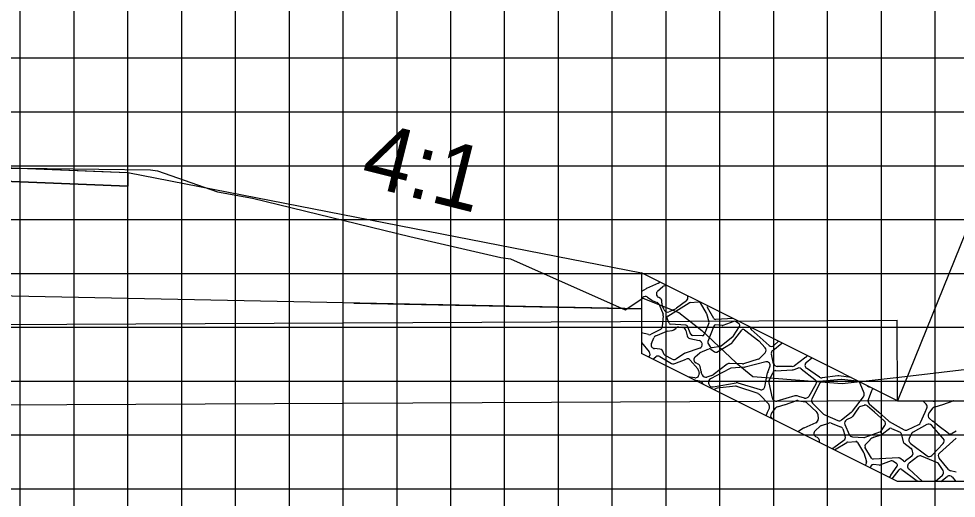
# Model space of a CAD drawing. Extents: x 851348 to 851692, y 364785 to 365005.
# Drawn here: x 851532.16 to 851549.58, y 364815.06 to 364823.96 of the extents above; entities that cross this region are included whole.
import ezdxf

# ---------------------------------------------------------------- set-up
doc = ezdxf.new("R2010")
doc.units = 0
for name, color, linetype in [('ANNOTATION', 7, 'Continuous'), ('D_Drainage_Culvert', 7, 'Continuous'), ('D_Roadway_Centerline', 7, 'Continuous'), ('D_Roadway_Edge_Shoulder', 7, 'Continuous'), ('D_Roadway_SubGrade', 7, 'Continuous'), ('MAJOR', 7, 'Continuous'), ('MINOR', 7, 'Continuous'), ('S_Roadway_Centerline', 7, 'Continuous')]:
    doc.layers.add(name, color=color, linetype=linetype)

msp = doc.modelspace()

# ---------------------------------------------------------------- linework, layer by layer
at = {"layer": 'ANNOTATION'}
for p, q in [((851545.52, 364818.351), (851543.731, 364819.245)), ((851543.731, 364819.245), (851543.731, 364817.745)), ((851538.389, 364818.681), (851543.731, 364818.574))]:
    msp.add_line(p, q, dxfattribs=at)
for points in [[(851556.942, 364823.691), (851551.251, 364823.691), (851548.49, 364816.866)], [(851534.191, 364821.105), (851543.731, 364819.245)], [(851548.49, 364816.866), (851550.49, 364816.866), (851552.49, 364817.866), (851556.563, 364819.902)], [(851548.49, 364816.866), (851546.49, 364817.866), (851545.52, 364818.351)], [(851548.49, 364815.366), (851543.731, 364817.745)], [(851550.49, 364815.366), (851548.49, 364815.366)]]:
    msp.add_lwpolyline(points, dxfattribs=at)
at = {"layer": 'D_Drainage_Culvert'}
for p, q in [((851480.479, 364818.026), (851548.483, 364818.366)), ((851548.49, 364816.866), (851548.483, 364818.366)), ((851548.49, 364816.866), (851480.463, 364816.525))]:
    msp.add_line(p, q, dxfattribs=at)
at = {"layer": 'D_Roadway_Centerline'}
msp.add_lwpolyline([(851485.104, 364818.833), (851493.575, 364820.951), (851494.191, 364821.105), (851501.707, 364821.405), (851502.191, 364821.425), (851513.465, 364821.65), (851514.191, 364821.665), (851525.465, 364821.439), (851526.191, 364821.425), (851533.707, 364821.124), (851534.191, 364821.105), (851543.731, 364819.245)], dxfattribs=at)
at = {"layer": 'D_Roadway_Edge_Shoulder'}
msp.add_lwpolyline([(851526.191, 364821.425), (851534.191, 364821.105), (851534.191, 364820.855), (851526.191, 364821.175)], close=True, dxfattribs=at)
at = {"layer": 'D_Roadway_SubGrade'}
for p, q in [((851543.819, 364818.948), (851543.731, 364818.896)), ((851544.049, 364819.051), (851543.826, 364818.951)), ((851544.033, 364818.902), (851544.129, 364818.986)), ((851544.152, 364818.999), (851544.195, 364819.013)), ((851543.731, 364818.761), (851543.759, 364818.786)), ((851543.843, 364818.79), (851543.922, 364818.734)), ((851544.076, 364818.774), (851544.046, 364818.79)), ((851544.586, 364818.818), (851544.592, 364818.8)), ((851543.934, 364818.728), (851544.023, 364818.689)), ((851544.059, 364818.652), (851544.133, 364818.474)), ((851544.119, 364818.643), (851544.113, 364818.72)), ((851544.154, 364818.556), (851544.125, 364818.622)), ((851544.221, 364818.44), (851544.62, 364818.685)), ((851544.37, 364818.576), (851544.244, 364818.52)), ((851544.568, 364818.723), (851544.384, 364818.584)), ((851544.635, 364818.69), (851544.791, 364818.702)), ((851544.823, 364818.686), (851544.935, 364818.496)), ((851545.079, 364818.392), (851544.96, 364818.599)), ((851544.138, 364818.442), (851544.12, 364818.246)), ((851544.244, 364818.308), (851544.207, 364818.397)), ((851544.938, 364818.489), (851544.986, 364818.33)), ((851545.438, 364818.392), (851545.111, 364818.374)), ((851544.557, 364818.271), (851544.274, 364818.287)), ((851544.336, 364818.184), (851544.374, 364818.217)), ((851544.425, 364818.233), (851544.498, 364818.225)), ((851544.652, 364818.1), (851544.586, 364818.25)), ((851544.985, 364818.307), (851544.9, 364818.095)), ((851545.075, 364818.253), (851544.965, 364817.968)), ((851545.231, 364818.263), (851545.11, 364818.274)), ((851545.449, 364818.34), (851545.246, 364818.265)), ((851545.442, 364818.074), (851545.556, 364818.245)), ((851545.547, 364818.292), (851545.48, 364818.337)), ((851543.864, 364818.095), (851543.731, 364818.13)), ((851544.084, 364818.192), (851543.914, 364818.101)), ((851543.998, 364818.072), (851544.191, 364818.153)), ((851544.209, 364818.157), (851544.3, 364818.169)), ((851544.558, 364818.172), (851544.579, 364818.075)), ((851544.867, 364818.074), (851544.682, 364818.08)), ((851545.216, 364817.889), (851545.435, 364818.066)), ((851545.424, 364817.953), (851545.596, 364818.178)), ((851545.644, 364818.184), (851545.91, 364817.981)), ((851545.773, 364818.191), (851546.102, 364817.894)), ((851543.731, 364817.95), (851543.877, 364817.773)), ((851543.916, 364817.932), (851543.962, 364818.037)), ((851544.632, 364818.022), (851544.803, 364817.987)), ((851544.856, 364817.936), (851544.858, 364817.925)), ((851544.968, 364817.938), (851545.008, 364817.87)), ((851545.043, 364817.854), (851545.2, 364817.882)), ((851545.13, 364817.771), (851545.415, 364817.945)), ((851545.915, 364817.977), (851546.03, 364817.852)), ((851546.17, 364817.802), (851546.343, 364817.939)), ((851546.193, 364817.893), (851546.281, 364817.97)), ((851544.074, 364817.826), (851543.972, 364817.836)), ((851544.135, 364817.761), (851544.135, 364817.766)), ((851544.304, 364817.638), (851544.171, 364817.709)), ((851544.533, 364817.744), (851544.373, 364817.641)), ((851544.815, 364817.845), (851544.547, 364817.751)), ((851544.73, 364817.682), (851544.815, 364817.759)), ((851544.825, 364817.765), (851544.987, 364817.828)), ((851545.02, 364817.824), (851545.092, 364817.772)), ((851546.03, 364817.758), (851545.932, 364817.655)), ((851546.188, 364817.555), (851546.146, 364817.732)), ((851543.945, 364817.638), (851543.997, 364817.681)), ((851544.074, 364817.687), (851544.292, 364817.561)), ((851544.351, 364817.556), (851544.563, 364817.639)), ((851544.64, 364817.62), (851544.777, 364817.46)), ((851544.787, 364817.548), (851544.744, 364817.57)), ((851545.326, 364817.545), (851545.063, 364817.347)), ((851545.609, 364817.552), (851545.369, 364817.558)), ((851545.902, 364817.637), (851545.631, 364817.555)), ((851546.04, 364817.587), (851545.656, 364817.492)), ((851546.656, 364817.576), (851546.574, 364817.517)), ((851546.789, 364817.674), (851546.656, 364817.576)), ((851546.795, 364817.579), (851546.898, 364817.662)), ((851544.793, 364817.427), (851544.802, 364817.373)), ((851544.841, 364817.409), (851544.822, 364817.501)), ((851544.862, 364817.349), (851544.844, 364817.4)), ((851545.366, 364817.462), (851545.012, 364817.275)), ((851545.645, 364817.491), (851545.393, 364817.47)), ((851546.024, 364817.127), (851546.076, 364817.386)), ((851546.08, 364817.399), (851546.12, 364817.495)), ((851546.106, 364817.24), (851546.17, 364817.384)), ((851546.23, 364817.425), (851546.532, 364817.438)), ((851546.534, 364817.504), (851546.255, 364817.503)), ((851546.552, 364817.442), (851546.636, 364817.471)), ((851546.701, 364817.461), (851546.956, 364817.263)), ((851547.042, 364817.302), (851546.799, 364817.469)), ((851544.725, 364817.294), (851544.596, 364817.313)), ((851544.816, 364817.231), (851544.742, 364817.24)), ((851544.878, 364817.172), (851544.872, 364817.188)), ((851545.042, 364817.336), (851544.947, 364817.307)), ((851544.978, 364817.196), (851544.984, 364817.173)), ((851545.062, 364817.124), (851545.491, 364817.201)), ((851545.523, 364817.199), (851545.938, 364817.074)), ((851546.164, 364816.912), (851546.102, 364817.197)), ((851546.973, 364817.175), (851546.841, 364816.948)), ((851547.047, 364817.193), (851546.898, 364816.901)), ((851547.379, 364817.331), (851547.09, 364817.291)), ((851547.442, 364817.264), (851547.101, 364817.23)), ((851547.628, 364817.297), (851547.399, 364817.331)), ((851547.741, 364817.231), (851547.457, 364817.264)), ((851547.867, 364817.006), (851547.797, 364817.188)), ((851545.477, 364817.137), (851545.137, 364817.098)), ((851545.9, 364816.998), (851545.507, 364817.133)), ((851548.005, 364817.053), (851547.944, 364816.884)), ((851546.096, 364816.803), (851545.927, 364816.98)), ((851546.584, 364816.957), (851546.25, 364816.861)), ((851546.409, 364816.797), (851546.601, 364816.865)), ((851546.656, 364816.947), (851546.622, 364816.957)), ((851546.636, 364816.868), (851546.656, 364816.865)), ((851546.763, 364816.916), (851546.656, 364816.947)), ((851546.656, 364816.865), (851546.772, 364816.845)), ((851546.807, 364816.827), (851546.984, 364816.662)), ((851547.651, 364816.674), (851547.857, 364816.939)), ((851549.02, 364816.803), (851548.96, 364816.866)), ((851549.19, 364816.866), (851549.174, 364816.861)), ((851549.334, 364816.797), (851549.526, 364816.865)), ((851549.575, 364816.866), (851549.58, 364816.865)), ((851546.048, 364816.587), (851546.076, 364816.653)), ((851546.076, 364816.653), (851546.109, 364816.729)), ((851546.146, 364816.63), (851546.164, 364816.653)), ((851546.164, 364816.653), (851546.226, 364816.733)), ((851546.262, 364816.756), (851546.404, 364816.795)), ((851546.91, 364816.821), (851547.078, 364816.653)), ((851547.078, 364816.653), (851547.115, 364816.617)), ((851547.451, 364816.511), (851547.628, 364816.653)), ((851547.628, 364816.653), (851547.64, 364816.662)), ((851547.709, 364816.653), (851547.66, 364816.58)), ((851547.765, 364816.734), (851547.709, 364816.653)), ((851547.867, 364816.781), (851547.801, 364816.761)), ((851548.062, 364816.653), (851547.931, 364816.767)), ((851547.963, 364816.81), (851548.139, 364816.653)), ((851548.243, 364816.495), (851548.062, 364816.653)), ((851548.139, 364816.653), (851548.32, 364816.491)), ((851548.918, 364816.461), (851549.001, 364816.653)), ((851549.001, 364816.653), (851549.033, 364816.729)), ((851549.071, 364816.63), (851549.089, 364816.653)), ((851549.089, 364816.653), (851549.151, 364816.733)), ((851549.187, 364816.756), (851549.329, 364816.795)), ((851546.164, 364816.528), (851546.157, 364816.534)), ((851547.006, 364816.619), (851547.014, 364816.527)), ((851547.137, 364816.602), (851547.382, 364816.501)), ((851547.634, 364816.557), (851547.542, 364816.511)), ((851548.333, 364816.482), (851548.613, 364816.329)), ((851549.142, 364816.486), (851549.082, 364816.534)), ((851549.262, 364816.389), (851549.143, 364816.486)), ((851546.656, 364816.303), (851546.637, 364816.292)), ((851546.743, 364816.355), (851546.656, 364816.303)), ((851546.974, 364816.458), (851546.75, 364816.359)), ((851546.958, 364816.31), (851547.054, 364816.394)), ((851547.077, 364816.407), (851547.211, 364816.452)), ((851547.257, 364816.451), (851547.431, 364816.384)), ((851547.471, 364816.342), (851547.517, 364816.208)), ((851547.51, 364816.423), (851547.591, 364816.237)), ((851548.191, 364816.312), (851548.255, 364816.406)), ((851548.213, 364816.254), (851548.34, 364816.349)), ((851548.375, 364816.353), (851548.537, 364816.281)), ((851548.675, 364816.327), (851548.885, 364816.427)), ((851549.034, 364816.425), (851548.779, 364816.285)), ((851549.34, 364816.163), (851549.118, 364816.41)), ((851549.431, 364816.264), (851549.264, 364816.387)), ((851549.58, 364816.303), (851549.506, 364816.26)), ((851547.001, 364816.182), (851546.971, 364816.198)), ((851547.041, 364816.09), (851547.037, 364816.128)), ((851547.493, 364816.131), (851547.308, 364815.992)), ((851547.65, 364816.196), (851547.862, 364816.184)), ((851547.89, 364816.188), (851548.158, 364816.286)), ((851547.89, 364816.047), (851547.978, 364816.143)), ((851548.047, 364816.188), (851548.167, 364816.23)), ((851548.557, 364816.258), (851548.595, 364816.101)), ((851548.751, 364816.255), (851548.707, 364816.166)), ((851549.268, 364815.895), (851549.58, 364816.169)), ((851547.295, 364815.984), (851547.273, 364815.974)), ((851547.317, 364815.952), (851547.545, 364816.092)), ((851547.56, 364816.097), (851547.715, 364816.11)), ((851547.748, 364816.093), (851547.859, 364815.904)), ((851548.004, 364815.799), (851547.885, 364816.007)), ((851548.608, 364816.082), (851548.744, 364815.982)), ((851548.726, 364816.081), (851549.038, 364815.843)), ((851548.757, 364815.96), (851548.771, 364815.871)), ((851549.129, 364815.85), (851549.338, 364816.07)), ((851547.863, 364815.896), (851547.911, 364815.738)), ((851548.508, 364815.807), (851548.035, 364815.782)), ((851548.598, 364815.748), (851548.531, 364815.8)), ((851548.758, 364815.839), (851548.64, 364815.748)), ((851548.869, 364815.828), (851548.703, 364815.704)), ((851549.23, 364815.711), (851548.937, 364815.836)), ((851549.438, 364815.588), (851549.261, 364815.8)), ((851547.91, 364815.715), (851547.89, 364815.666)), ((851547.999, 364815.661), (851547.983, 364815.619)), ((851548.156, 364815.671), (851548.035, 364815.682)), ((851548.374, 364815.748), (851548.171, 364815.673)), ((851548.367, 364815.481), (851548.481, 364815.653)), ((851548.472, 364815.7), (851548.405, 364815.745)), ((851549.336, 364815.57), (851549.261, 364815.685)), ((851548.327, 364815.447), (851548.36, 364815.474)), ((851548.39, 364815.415), (851548.521, 364815.586)), ((851548.569, 364815.592), (851548.835, 364815.389)), ((851548.698, 364815.599), (851548.956, 364815.366)), ((851549.191, 364815.366), (851549.323, 364815.481)), ((851549.291, 364815.366), (851549.41, 364815.46)), ((851549.58, 364815.538), (851549.473, 364815.566)), ((851549.505, 364815.45), (851549.574, 364815.366)), ((851548.839, 364815.385), (851548.857, 364815.366))]:
    msp.add_line(p, q, dxfattribs=at)
msp.add_lwpolyline([(851485.104, 364818.833), (851494.191, 364821.105), (851494.191, 364820.855), (851502.191, 364821.175), (851514.191, 364821.415), (851526.191, 364821.175), (851534.191, 364820.855), (851534.191, 364821.105), (851543.731, 364819.245), (851543.731, 364818.574), (851526.191, 364818.925), (851514.191, 364819.165), (851502.191, 364818.925), (851485.104, 364818.583)], dxfattribs=at)
for centre, radius, start, end in [((851543.853, 364818.889), 0.0684, 113.9625, 120.6507), ((851544.021, 364819.113), 0.0684, 293.9625, 323.5047), ((851544.174, 364818.934), 0.0684, 108.4349, 131.1859), ((851543.804, 364818.734), 0.0684, 54.7824, 131.257), ((851544.078, 364818.85), 0.0684, 131.1859, 242.3005), ((851544.044, 364818.714), 0.0684, 5.1944, 62.3005), ((851544.527, 364818.778), 0.0684, 307.0199, 18.7413), ((851543.962, 364818.79), 0.0684, 234.7824, 246.3706), ((851543.996, 364818.626), 0.0684, 22.4794, 66.3706), ((851544.188, 364818.649), 0.0684, 185.1944, 203.3852), ((851544.343, 364818.639), 0.0684, 293.8602, 307.0199), ((851544.638, 364818.655), 0.0342, 94.6669, 121.5514), ((851544.793, 364818.668), 0.0342, 30.5102, 94.6669), ((851544.99, 364818.616), 0.0342, 154.1739, 209.792), ((851544.07, 364818.448), 0.0684, 354.8056, 22.4794), ((851544.216, 364818.583), 0.0684, 203.3852, 293.8602), ((851544.239, 364818.411), 0.0342, 121.5514, 202.6199), ((851544.905, 364818.479), 0.0342, 16.9275, 30.5102), ((851545.109, 364818.409), 0.0342, 209.792, 272.9903), ((851544.052, 364818.252), 0.0684, 298.0725, 354.8056), ((851544.276, 364818.321), 0.0342, 202.6199, 266.6726), ((851544.418, 364818.165), 0.0684, 84.2894, 130.3645), ((851544.491, 364818.157), 0.0684, 12.4074, 84.2894), ((851544.555, 364818.237), 0.0342, 23.7495, 86.6726), ((851544.953, 364818.32), 0.0342, 338.1986, 16.9275), ((851545.107, 364818.24), 0.0342, 84.4278, 159.0071), ((851545.234, 364818.297), 0.0342, 264.4278, 290.4835), ((851545.461, 364818.308), 0.0342, 56.3099, 110.4835), ((851545.528, 364818.264), 0.0342, 326.3099, 56.3099), ((851545.819, 364818.242), 0.0684, 185.3373, 227.8776), ((851543.881, 364818.161), 0.0684, 255.2564, 298.0725), ((851544.025, 364818.009), 0.0684, 112.6199, 156.3179), ((851544.218, 364818.089), 0.0684, 97.125, 112.6199), ((851544.292, 364818.237), 0.0684, 277.125, 310.3645), ((851544.646, 364818.089), 0.0684, 192.4074, 258.3664), ((851544.683, 364818.114), 0.0342, 203.7495, 268.1221), ((851544.868, 364818.108), 0.0342, 268.1221, 338.1986), ((851545.414, 364818.093), 0.0342, 308.7742, 326.3099), ((851545.623, 364818.157), 0.0342, 52.5946, 142.5946), ((851543.979, 364817.904), 0.0684, 156.3179, 263.9458), ((851544.789, 364817.92), 0.0684, 13.134, 78.3664), ((851544.792, 364817.909), 0.0684, 289.406, 13.134), ((851544.997, 364817.955), 0.0342, 159.0071, 210.6507), ((851545.037, 364817.888), 0.0342, 210.6507, 280.204), ((851545.194, 364817.916), 0.0342, 280.204, 308.7742), ((851545.397, 364817.974), 0.0342, 301.373, 322.5946), ((851545.89, 364817.954), 0.0342, 42.7891, 52.5946), ((851546.148, 364817.944), 0.0684, 227.8776, 311.2462), ((851543.824, 364817.729), 0.0684, 309.6391, 39.4712), ((851544.04, 364817.628), 0.0684, 59.9314, 128.8845), ((851544.067, 364817.758), 0.0684, 6.8428, 83.9458), ((851544.203, 364817.769), 0.0684, 186.8428, 242.1524), ((851544.57, 364817.686), 0.0684, 109.406, 122.6806), ((851544.838, 364817.734), 0.0342, 111.1941, 132.2073), ((851545, 364817.796), 0.0342, 54.4623, 111.1941), ((851545.112, 364817.8), 0.0342, 234.4623, 301.373), ((851545.98, 364817.805), 0.0684, 316.3639, 42.7891), ((851546.212, 364817.748), 0.0684, 128.373, 193.5819), ((851546.749, 364817.729), 0.0684, 306.2192, 338.5394), ((851544.326, 364817.62), 0.0684, 239.9314, 291.541), ((851544.336, 364817.699), 0.0684, 242.1524, 302.6806), ((851544.588, 364817.576), 0.0684, 40.6013, 111.541), ((851544.776, 364817.631), 0.0684, 132.2073, 242.354), ((851544.755, 364817.487), 0.0684, 11.6336, 62.354), ((851545.367, 364817.49), 0.0684, 88.4306, 126.9888), ((851545.611, 364817.62), 0.0684, 268.4306, 286.8986), ((851545.882, 364817.702), 0.0684, 286.8986, 316.3639), ((851546.057, 364817.521), 0.0684, 337.4775, 103.8595), ((851546.255, 364817.572), 0.0684, 193.5819, 270.0888), ((851546.838, 364817.526), 0.0684, 128.8845, 235.4375), ((851544.735, 364817.361), 0.0684, 261.5289, 10.3048), ((851544.725, 364817.415), 0.0684, 10.3048, 40.6013), ((851544.908, 364817.423), 0.0684, 191.6336, 199.5367), ((851544.926, 364817.372), 0.0684, 199.5367, 287.2815), ((851545.022, 364817.402), 0.0684, 287.2815, 306.9888), ((851545.398, 364817.401), 0.0684, 94.7636, 117.8015), ((851545.64, 364817.559), 0.0684, 274.7636, 283.8595), ((851546.143, 364817.373), 0.0684, 157.4775, 168.7067), ((851546.233, 364817.357), 0.0684, 92.4366, 156.0375), ((851546.529, 364817.506), 0.0684, 272.4366, 289.44), ((851546.534, 364817.572), 0.0684, 270.0888, 306.2192), ((851546.659, 364817.407), 0.0684, 92.6788, 109.44), ((851546.659, 364817.407), 0.0684, 52.3058, 92.6788), ((851544.808, 364817.163), 0.0684, 20.9245, 83.5169), ((851545.044, 364817.214), 0.0684, 117.8015, 195.5241), ((851545.05, 364817.191), 0.0684, 195.5241, 280.1543), ((851545.503, 364817.134), 0.0684, 73.267, 100.1543), ((851546.168, 364817.212), 0.0684, 156.0375, 192.4074), ((851546.914, 364817.209), 0.0684, 329.8265, 52.3058), ((851547.081, 364817.358), 0.0684, 235.4375, 277.9435), ((851547.108, 364817.162), 0.0684, 95.5993, 152.9691), ((851547.389, 364817.263), 0.0684, 81.5289, 97.9435), ((851547.449, 364817.196), 0.0684, 83.5169, 95.5993), ((851547.733, 364817.163), 0.0684, 20.9245, 83.5169), ((851545.145, 364817.03), 0.0684, 96.5245, 147.0214), ((851545.485, 364817.069), 0.0684, 70.9362, 96.5245), ((851545.877, 364816.933), 0.0684, 43.5732, 70.9362), ((851545.957, 364817.14), 0.0684, 253.267, 348.7067), ((851547.803, 364816.981), 0.0684, 322.2243, 20.9245), ((851547.975, 364817.191), 0.0684, 216.5608, 270.3091), ((851548.07, 364817.03), 0.0684, 116.2669, 160.0795), ((851546.231, 364816.927), 0.0684, 192.4074, 285.9454), ((851546.603, 364816.891), 0.0684, 74.0546, 105.9454), ((851546.624, 364816.801), 0.0684, 80.1342, 109.6538), ((851546.782, 364816.982), 0.0684, 254.0546, 329.8265), ((851546.76, 364816.777), 0.0684, 47.1211, 80.1342), ((851546.959, 364816.869), 0.0684, 152.9691, 225), ((851548.009, 364816.861), 0.0684, 160.0795, 228.2412), ((851549.156, 364816.927), 0.0684, 243.4668, 285.9454), ((851549.549, 364816.801), 0.0684, 108.6645, 109.6538), ((851546.046, 364816.756), 0.0684, 336.6444, 43.5732), ((851546.28, 364816.69), 0.0684, 105.2551, 141.953), ((851546.386, 364816.861), 0.0684, 285.2551, 289.6538), ((851546.938, 364816.612), 0.0684, 36.5817, 47.1211), ((851546.938, 364816.612), 0.0684, 5.1944, 36.5817), ((851547.597, 364816.716), 0.0684, 308.6598, 322.2243), ((851547.821, 364816.696), 0.0684, 106.8584, 145.7843), ((851547.887, 364816.716), 0.0684, 48.8937, 106.8584), ((851548.971, 364816.756), 0.0684, 336.6444, 43.5732), ((851549.205, 364816.69), 0.0684, 105.2551, 141.953), ((851549.311, 364816.861), 0.0684, 285.2551, 289.6538), ((851546.2, 364816.588), 0.0684, 141.953, 231.3402), ((851546.946, 364816.521), 0.0684, 293.9625, 5.1944), ((851547.163, 364816.665), 0.0684, 225, 247.6938), ((851547.408, 364816.564), 0.0684, 247.6938, 308.6598), ((851547.572, 364816.45), 0.0684, 116.5651, 203.7495), ((851547.603, 364816.618), 0.0684, 296.5651, 325.7843), ((851548.198, 364816.444), 0.0684, 326.0035, 48.8937), ((851548.366, 364816.542), 0.0684, 228.2412, 241.294), ((851549.125, 364816.588), 0.0684, 141.953, 231.3402), ((851549.099, 364816.433), 0.0684, 50.9061, 51.3402), ((851546.778, 364816.297), 0.0684, 113.9625, 120.6507), ((851547.003, 364816.258), 0.0684, 131.1859, 242.3005), ((851547.099, 364816.342), 0.0684, 108.4349, 131.1859), ((851547.232, 364816.387), 0.0684, 69.0265, 108.4349), ((851547.406, 364816.32), 0.0684, 18.7413, 69.0265), ((851548.135, 364816.35), 0.0684, 289.9256, 326.0035), ((851548.361, 364816.322), 0.0342, 66.1398, 126.7644), ((851548.646, 364816.389), 0.0684, 241.294, 295.4039), ((851548.855, 364816.488), 0.0684, 295.4039, 336.6444), ((851549.067, 364816.365), 0.0684, 41.8334, 118.7575), ((851549.305, 364816.442), 0.0684, 230.9061, 233.4711), ((851546.969, 364816.121), 0.0684, 5.1944, 62.3005), ((851547.452, 364816.186), 0.0684, 307.0199, 18.7413), ((851547.654, 364816.265), 0.0684, 203.7495, 266.7755), ((851547.866, 364816.253), 0.0684, 266.7755, 289.9256), ((851548.103, 364816.027), 0.171, 109.1336, 137.3215), ((851548.111, 364816.391), 0.171, 289.1336, 306.7644), ((851548.524, 364816.25), 0.0342, 13.7608, 66.1398), ((851548.768, 364816.136), 0.0684, 153.4931, 232.6367), ((851548.812, 364816.225), 0.0684, 118.7575, 153.4931), ((851549.289, 364816.117), 0.0684, 316.4321, 41.8334), ((851549.472, 364816.319), 0.0684, 233.4711, 300.6507), ((851547.267, 364816.046), 0.0684, 293.8602, 307.0199), ((851547.562, 364816.063), 0.0342, 94.6669, 121.5514), ((851547.718, 364816.076), 0.0342, 30.5102, 94.6669), ((851547.915, 364816.024), 0.0342, 137.3215, 209.792), ((851548.628, 364816.109), 0.0342, 193.7608, 233.6864), ((851548.723, 364815.955), 0.0342, 8.7462, 53.6864), ((851547.83, 364815.886), 0.0342, 16.9275, 30.5102), ((851548.034, 364815.816), 0.0342, 209.792, 272.9903), ((851548.51, 364815.773), 0.0342, 52.4314, 92.9903), ((851548.737, 364815.866), 0.0342, 307.5348, 8.7462), ((851548.91, 364815.773), 0.0684, 66.9778, 126.6071), ((851549.08, 364815.897), 0.0684, 232.6367, 316.4321), ((851549.313, 364815.844), 0.0684, 131.257, 219.9575), ((851547.878, 364815.728), 0.0342, 338.1986, 16.9275), ((851548.031, 364815.648), 0.0342, 84.4278, 159.0071), ((851548.159, 364815.705), 0.0342, 264.4278, 290.4835), ((851548.386, 364815.716), 0.0342, 56.3099, 110.4835), ((851548.453, 364815.672), 0.0342, 326.3099, 56.3099), ((851548.619, 364815.775), 0.0342, 232.4314, 307.5348), ((851548.744, 364815.649), 0.0684, 126.6071, 227.8776), ((851549.204, 364815.648), 0.0684, 32.9625, 66.9778), ((851548.338, 364815.5), 0.0342, 308.7742, 326.3099), ((851548.548, 364815.565), 0.0342, 52.5946, 142.5946), ((851549.278, 364815.533), 0.0684, 311.2462, 32.9625), ((851549.452, 364815.406), 0.0684, 39.4712, 128.373), ((851549.491, 364815.632), 0.0684, 219.9575, 255.2564), ((851548.814, 364815.361), 0.0342, 42.7891, 52.5946)]:
    msp.add_arc(centre, radius, start, end, dxfattribs=at)
at = {"layer": 'MAJOR'}
for p, q in [((851534.191, 364808.233), (851534.191, 364838.233)), ((851544.191, 364808.233), (851544.191, 364838.233)), ((851374.191, 364823.233), (851654.191, 364823.233)), ((851374.191, 364818.233), (851654.191, 364818.233))]:
    msp.add_line(p, q, dxfattribs=at)
at = {"layer": 'MINOR'}
for p, q in [((851532.191, 364808.233), (851532.191, 364838.233)), ((851533.191, 364808.233), (851533.191, 364838.233)), ((851535.191, 364808.233), (851535.191, 364838.233)), ((851536.191, 364808.233), (851536.191, 364838.233)), ((851537.191, 364808.233), (851537.191, 364838.233)), ((851538.191, 364808.233), (851538.191, 364838.233)), ((851539.191, 364808.233), (851539.191, 364838.233)), ((851540.191, 364808.233), (851540.191, 364838.233)), ((851541.191, 364808.233), (851541.191, 364838.233)), ((851542.191, 364808.233), (851542.191, 364838.233)), ((851543.191, 364808.233), (851543.191, 364838.233)), ((851545.191, 364808.233), (851545.191, 364838.233)), ((851546.191, 364808.233), (851546.191, 364838.233)), ((851547.191, 364808.233), (851547.191, 364838.233)), ((851548.191, 364808.233), (851548.191, 364838.233)), ((851549.191, 364808.233), (851549.191, 364838.233)), ((851374.191, 364822.233), (851654.191, 364822.233)), ((851374.191, 364821.233), (851654.191, 364821.233)), ((851374.191, 364820.233), (851654.191, 364820.233)), ((851374.191, 364819.233), (851654.191, 364819.233)), ((851374.191, 364817.233), (851654.191, 364817.233)), ((851374.191, 364816.233), (851654.191, 364816.233)), ((851374.191, 364815.233), (851654.191, 364815.233))]:
    msp.add_line(p, q, dxfattribs=at)
at = {"layer": 'S_Roadway_Centerline'}
msp.add_lwpolyline([(851528.153, 364821.217), (851532.695, 364821.183), (851534.614, 364821.155), (851534.741, 364821.138), (851535.856, 364820.75), (851536.504, 364820.632), (851539.427, 364819.92), (851541.118, 364819.528), (851541.299, 364819.5), (851543.429, 364818.558), (851543.759, 364818.774), (851544.424, 364818.506), (851544.854, 364818.171), (851545.494, 364817.569), (851545.801, 364817.315), (851546.992, 364817.226), (851547.458, 364817.185), (851548.519, 364817.304), (851550.09, 364817.488), (851550.223, 364817.565), (851551.866, 364818.366), (851555.144, 364819.274), (851560.825, 364821.765)], dxfattribs=at)

# ---------------------------------------------------------------- texts
at = {"layer": 'ANNOTATION'}
msp.add_text('4:1', height=1.2, rotation=345.9638, dxfattribs=at).set_placement((851538.476, 364820.895))

doc.saveas('drawing.dxf')
